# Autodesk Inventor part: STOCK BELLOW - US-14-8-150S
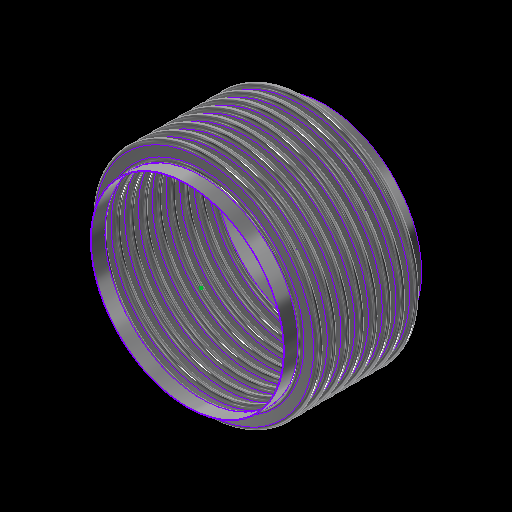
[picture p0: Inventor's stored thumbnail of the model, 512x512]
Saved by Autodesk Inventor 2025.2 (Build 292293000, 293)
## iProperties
Category: 16 GA (0.060 THICK)
RuleStatus: InUse
Created: 2024-01
Part Number: STOCK BELLOW - US-14-8-150S
Project: =STOCK BELLOWS: <Stock Number><SFILL>
Material: ASTM A240-304
Description: =STOCK BELLOWS: <Stock Number>, <SID_> I.D., <SOD_> O.D., <SPLY_> PLY, <Category>, <SNET_CONS> CONS.<PITCH_><STANGENT_> TANGENT<SFILL>
Document SubType Name: Sheet Metal
Designer: GS
Stock Number: U.S-14-8-150S
Surface Area: 15835.5 cm^2
Volume: 1198.85 cm^3
Sheet Metal Rule: Default
Appearance: STAINLESS STEEL
Mass: 9659.48 g
Density: 8.05729 g/cm^3
THK: 0.036
ID: 3.500
OD: 4.250
CONS_: 2
PITCH: 0.500
TANGENT: 0.500
BELLOWS_UPSET: 0.000
d79: 1.000
d82: 1.000
d83: 26.000
d84: 24.000
d174: 8
d214: 8
STHK_: 0.060
SID_: 14.000
SOD_: 16.500
SPITCH_: 1.000
STANGENT__: 1.000
SBELLOWS_UPSET_: 0.000
SDIFF_TAN: 1.000
d252: 2
d275: 2
d287: 0.050
d289: 0.500
d290: 0.000
SOD_NECK: 14 1/8
PLY: 1
PSET: 4.178
PBAR: 1.035
COUNTER: 1.500
NET_TUBE: 3.071
CONS: 2
S_CONS: 0
NET_CONS: 2
ID_M: 88.90 mm
OD_M: 107.95 mm
THK_M: 0.91 mm
ID_U: 3.500 in
OD_U: 4.250 in
THK_U: 0.036 in
TANGENT2: 0.500
TAN_TO_TAN: 1.000 in
d80: 2.571
d81: 10
SID: 2.375
SCONS_: 8
SPITCH: 0.250
STANGENT_: 1.000
SBELLOWS_UPSET: 0.000
SNET_CONS: 8
SS_CONS: 0
SCONS: 8
d190: 8
d191: 1
d192: 1
d193: 8
d194: 0
SIZE: 14.00
PRESSURE: 150
d230: 8
STANGENT: 4.000
SPLY_: 1
d233: 8
d234: 0
d263: 2
d265: 1
d268: 2
d269: 0
d286: 2
d288: 1
d291: 2
d292: 0
SREROLL: 0.750
BLETP: 0.000 ul
PRES_Copy: 85
MATTABLE: 20 GA (0.036 THICK)
PART_NUMBER: U.S-14-8-150S
PITCH_: =, <SPITCH_> PITCH,
CFILL: .
SFILL: .
MESH: ,
COMP: 1.53
EXT: 0.77
LAT: 0.26
ANG: 573
ASR: 3894
LSR: 19100
ANSR: 1778
PRES: 150
COMPM: 15.3
EXTM: 7.65
LATM: 2.60
ASRM: 681.956
PRESM: 10.342
LSRM: 3344.983
ANSRM: 311.381
TEMPMIN: 20
TEMPMAX: 800
TEMPMINM: -7
TEMPMAXM: 427
WEIGHTM: 9.659
WEIGHT: 21.296
Author: GS
Keywords: 20 GA (0.036 THICK)
Comments: =STOCK BELLOW - <STOCK NUMBER>
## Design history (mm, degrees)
sketch "Sketch2"
  geometry: L1 (0, -177.245)-(0, 562.856) reference; L2 (45.364, 0)-(44.45, 0); L3 (48.082, -2.718)-(50.343, -2.718); L4 (48.082, -3.632)-(50.343, -3.632); L5 (50.343, -9.982)-(48.082, -9.982); L6 (50.343, -9.068)-(48.082, -9.068); L7 (45.364, -12.7)-(44.45, -12.7); L8 (48.082, 0)-(48.082, -12.7); L9 (50.343, -6.35)-(53.975, -6.35); L10 (44.45, 0)-(44.45, -12.7); L11 (20.376, 102.841)-(20.376, 101.926); L12 (58.262, 457.127)-(58.262, 349.177); L13 (58.262, 444.427)-(58.262, 336.477); L14 (93.133, -58.817)-(93.133, -71.517); L15 (118.746, -66.401)-(118.746, -66.401); L16 (50.343, -9.068)-(50.343, -9.982); L17 (48.082, -9.068)-(48.082, -9.982); L18 (48.082, -9.525)-(50.343, -9.525); L19 (53.975, 0)-(53.975, -12.7); L20 (-50.343, -9.068)-(-50.343, -9.982); L21 (-50.343, -2.718)-(-48.082, -2.718); L22 (-50.343, -3.632)-(-48.082, -3.632); L23 (-48.082, -9.068)-(-50.343, -9.068); L24 (-50.343, -9.525)-(-48.082, -9.525); L25 (-48.082, -9.982)-(-50.343, -9.982); L26 (-48.082, -9.068)-(-48.082, -9.982); L27 (-44.45, 0.653)-(-44.45, -12.047); L28 (-48.082, -6.35)-(-44.45, -6.35); L29 (-50.343, 0.653)-(-50.343, -12.7); L30 (-53.061, 0)-(-53.975, 0); L31 (-53.975, 0)-(-53.975, -12.7); L32 (-53.061, -12.7)-(-53.975, -12.7); A1 r 2.718 centre (48.082, 0) between (45.364, 0) and (48.082, -2.718); A2 r 3.632 centre (48.082, 0) between (44.45, 0) and (48.082, -3.632); A3 r 3.632 centre (50.343, -6.35) between (50.343, -9.982) and (50.343, -2.718); A4 r 2.718 centre (50.343, -6.35) between (50.343, -9.068) and (50.343, -3.632); A5 r 2.718 centre (48.082, -12.7) between (48.082, -9.982) and (45.364, -12.7); A6 r 3.632 centre (48.082, -12.7) between (48.082, -9.068) and (44.45, -12.7); A7 r 3.175 centre (50.343, -6.35) between (50.343, -9.525) and (53.518, -6.35); A8 r 3.175 centre (48.082, -12.7) between (48.082, -9.525) and (44.907, -12.7); A9 r 2.718 centre (-50.343, -12.7) between (-50.343, -9.982) and (-53.061, -12.7); A10 r 2.718 centre (-48.082, -6.35) between (-48.082, -9.068) and (-48.082, -3.632); A11 r 3.175 centre (-48.082, -6.35) between (-48.082, -9.525) and (-44.907, -6.35); A12 r 3.632 centre (-48.082, -6.35) between (-48.082, -9.982) and (-48.082, -2.718); A13 r 3.175 centre (-50.343, -12.7) between (-50.343, -9.525) and (-53.518, -12.7); A14 r 3.632 centre (-50.343, -12.7) between (-50.343, -9.068) and (-53.975, -12.7); A15 r 2.718 centre (-50.343, 0) between (-53.061, 0) and (-50.343, -2.718); A16 r 3.632 centre (-50.343, 0) between (-53.975, 0) and (-50.343, -3.632); 10 further points
  constraints: 62 end point, 38 point on circle, 20 tangent, 16 centre point, 12 parallel, 9 midpoint, 7 vertical, 6 coincident, 6 concentric, 6 point on line, 4 equal radius, 4 perpendicular, 3 horizontal, 1 collinear, 1 horizontal alignment, 10 other
  dimensions: "THK" = 0.9144 distance of L11.start L11.end; "ID" = 88.9 distance of L11.end point (20.376, 13.026); "OD" = 107.95 distance of L12.start L12.end; "PITCH" = 12.7 distance of L12.start L13.start; "TANGENT" = 12.7 distance of L14.start L14.end; "BELLOWS_UPSET" = 0 distance of L15.start L15.end; "d43" = 88.9 diameter of L10 L1 (= ID); "d44" = 107.95 diameter of L9.end L1 (= OD); "d45" = 0.9144 distance between parallel lines of L5 L6 (computed from THK, PLY); "d46" = 3.6322 radius of A3 (computed from PITCH, THK, PLY); "UPSET_PITCH" = 12.7 distance of L2.end L7.end (derived); "SIDEWALL_ANGLE" = 360 deg dimension on L3 L9 (derived); "CON_GAP" = 5.4356 distance of point (48.082, -9.068) point (48.082, -3.632) (derived); "TAN1" = 4.98728 dimension on A8 (derived); "TAN2" = 4.98728 dimension on A7 (derived); "LEG1" = 2.2606 distance of L18.start L18.end (derived); "d278" = 0.9144 distance between parallel lines of L25 L23 (derived); "d279" = 3.6322 radius of A12 (derived); "d280" = 12.7 distance of L30.end L31.end (derived); "d281" = 360 deg dimension on L21 L28 (derived); "d282" = 5.4356 distance of point (-50.343, -9.068) point (-50.343, -3.632) (derived); "d283" = 4.98728 dimension on A13 (derived); "d284" = 4.98728 dimension on A11 (derived); "d285" = 2.2606 distance of L24.start L24.end (derived); "d293" = 88.9 diameter of L27 L1 (derived); "d294" = 107.95 diameter of L31 L1 (derived)
  node "Sketch Rectangular Pattern1" dims "d31" = 25.4, "ID" = 88.9
  node "Sketch Rectangular Pattern2" dims "d39" = 25.4, "PITCH" = 12.7
revolve "CONS" stored, may be unused: angle "d48" = 90 deg
node "BELLOW MIDPLANE"
pattern_linear "Rectangular Pattern2" dims "d52" = 12.7 (= UPSET_PITCH)
sketch "Sketch5"
  geometry: C1 r 45.364 at (0, 0) reference; C2 r 44.45 at (0, 0) reference
extrude "TANGENT" new body sketch "Sketch5" distance "d53" = 12.7 (= TANGENT); taper "d54" = 0 deg
revolve "SAMETAN" stored, may be unused: angle "d65" = 90 deg
revolve "DIFFTAN" stored, may be unused: angle "d70" = 90 deg
sketch "Sketch9"
  geometry: L1 (53.319, 0)-(-53.319, 0) reference; L2 (0, -17.78)-(0, 17.78) reference; L3 (38.085, 0)-(-38.085, 0); L4 (38.085, -11.906)-(38.085, 11.906); L5 (25.385, -11.906)-(25.385, 11.906); L6 (13.15, 11.906)-(13.15, -11.906); L7 (-25.385, -11.906)-(-25.385, 11.906); L8 (-38.085, -11.906)-(-38.085, 11.906); L9 (37.291, -11.906)-(37.291, 11.906); L10 (38.085, -11.906)-(37.291, -11.906); L11 (38.085, 11.906)-(37.291, 11.906); L12 (13.546, 11.906)-(12.753, 11.906); L13 (12.753, 11.906)-(12.753, -11.906); L14 (12.753, -11.906)-(13.546, -11.906); L15 (13.546, -11.906)-(13.546, 11.906); L16 (-13.546, 11.906)-(-13.546, -11.906); L17 (-13.15, 11.906)-(-13.15, -11.906); L18 (-13.546, -11.906)-(-12.753, -11.906); L19 (-12.753, -11.906)-(-12.753, 11.906); L20 (-12.753, 11.906)-(-13.546, 11.906); L21 (-38.085, -11.906)-(-37.291, -11.906); L22 (-37.291, -11.906)-(-37.291, 11.906); L23 (-37.291, 11.906)-(-38.085, 11.906); L24 (-38.085, 11.906)-(-38.085, -11.906); L25 (38.085, -0.397)-(-38.085, -0.397); L26 (-38.085, -0.397)-(-38.085, 0.397); L27 (-38.085, 0.397)-(38.085, 0.397); L28 (38.085, 0.397)-(38.085, -0.397); L29 (-38.085, 11.906)-(38.085, 11.906); L30 (38.085, 11.906)-(38.085, 12.7); L31 (38.085, 12.7)-(-38.085, 12.7); L32 (-38.085, 12.7)-(-38.085, 11.906); L33 (38.085, -11.906)-(-38.085, -11.906); L34 (-38.085, -11.906)-(-38.085, -12.7); L35 (-38.085, -12.7)-(38.085, -12.7); L36 (38.085, -12.7)-(38.085, -11.906); 30 further points
  constraints: 68 end point, 13 midpoint, 13 parallel, 8 horizontal, 7 perpendicular, 6 equal length, 3 point on line, 2 vertical, 14 other
  dimensions: "d115" = 23.8125 distance of L4.start L4.end (derived); "d116" = 12.7 distance between parallel lines of L4 L5 (derived); "d117" = 12.23516 distance between parallel lines of L5 L6 (derived); "d125" = 38.53427 distance between parallel lines of L7 L6 (derived); "d127" = 12.7 distance between parallel lines of L8 L7 (derived); "d128" = 24.93516 distance between parallel lines of L6 L4 (derived); "d130" = 76.16943 distance between parallel lines of L8 L4 (derived); "RULER_THK" = 0.79375 distance between parallel lines of L4 L9; "d135" = 0.79375 distance of L13.end L14.end (derived); "d138" = 26.29911 distance of L13.end L16.end (derived); "d143" = 0.79375 distance of L22.end L8.end (derived); "d144" = 0.79375 distance between parallel lines of L27 L25 (derived)
extrude "RULER" join sketch "Sketch9" distance "d149" = 0.79375 (derived); taper "d150" = 0 deg
extrude "BARS" join sketch "Sketch9" distance "d151" = 0.79375 (derived); taper "d152" = 0 deg
pattern_linear "Rectangular Pattern4" dims "d155" = 26.29911 (derived)
sketch "Sketch13"
  geometry: L1 (93.149, -52.467)-(93.149, -77.867); L2 (179.324, 0)-(177.8, 0); L3 (179.324, -25.4)-(177.8, -25.4); L4 (202.438, -19.812)-(184.912, -19.812); L5 (202.438, -18.288)-(184.912, -18.288); L6 (202.438, -12.7)-(209.55, -12.7); L7 (184.912, -5.588)-(202.438, -5.588); L8 (184.912, 0)-(184.912, -25.4); L9 (177.8, 0)-(177.8, -25.4); L10 (58.254, -77.331)-(58.254, -496.431); L11 (58.254, -102.731)-(58.254, -521.831); L12 (58.254, -153.531)-(58.254, -572.631); L13 (58.254, -178.931)-(58.254, -598.031); L14 (58.254, -204.331)-(58.254, -623.431); L15 (58.254, -229.731)-(58.254, -648.831); L16 (58.254, -255.131)-(58.254, -674.231); L17 (58.254, -128.131)-(58.254, -547.231); L18 (20.376, 103.45)-(20.376, 101.926); L19 (184.912, -7.112)-(202.438, -7.112); L20 (0, -829.767)-(0, 258.986) reference; L21 (-41.91, 0)-(251.46, 0) reference; A1 r 5.588 centre (184.912, 0) between (179.324, 0) and (184.912, -5.588); A2 r 5.588 centre (184.912, -25.4) between (184.912, -19.812) and (179.324, -25.4); A3 r 7.112 centre (184.912, -25.4) between (184.912, -18.288) and (177.8, -25.4); A4 r 5.588 centre (202.438, -12.7) between (202.438, -18.288) and (202.438, -7.112); A5 r 7.112 centre (202.438, -12.7) between (202.438, -19.812) and (202.438, -5.588); A6 r 7.112 centre (184.912, 0) between (177.8, 0) and (184.912, -7.112); 6 further points; 1 other entity
  constraints: 38 end point, 15 point on circle, 9 tangent, 6 centre point, 6 parallel, 5 vertical alignment, 4 point on line, 4 vertical, 3 coincident, 3 concentric, 2 collinear, 2 equal radius, 1 horizontal, 1 perpendicular, 23 other
  dimensions: "SBELLOWS_UPSET_" = 0 distance of point (118.762, -66.401) point (118.762, -66.401); "STOTAL_THK_BELLOW__" = 1.524 distance between parallel lines of L4 L5 (derived); "d224" = 7.112 radius of A5 (derived); "d225" = 25.4 distance of L2.end L3.end (derived); "SSIDEWALL_ANGLE_" = 360 deg dimension on L7 L6 (derived); "SSCON_GAP_" = 11.176 distance of point (184.912, -18.288) point (184.912, -7.112) (derived); "d235" = 355.6 diameter of L9 L20 (derived); "d236" = 419.1 diameter of L6.end L20 (derived)
  node "Sketch Rectangular Pattern4" dims "d228" = 25.4
  node "Sketch Rectangular Pattern5" dims "d229" = 25.4
revolve "SBELLOW" stored, may be unused: angle "d197" = 90 deg
pattern_linear "Rectangular Pattern5" dims "d204" = 25.4 (derived)
revolve "STANGENT" stored, may be unused: angle "d240" = 90 deg
revolve "SSAMETAN" stored, may be unused: angle "d241" = 90 deg
revolve "SDIFFTAN" stored, may be unused: angle "d246" = 90 deg
revolve "INVCON" stored, may be unused: angle "d295" = 90 deg
pattern_linear "Rectangular Pattern6" dims "d298" = 12.7 (derived)
revolve "INVTANGENT" stored, may be unused: angle "d302" = 90 deg
revolve "INVSAMETAN" stored, may be unused: angle "d307" = 90 deg
revolve "INVDIFFTAN" stored, may be unused: angle "d312" = 90 deg
sketch "ID BELLOW MOUNT CALC"
  geometry: L1 (44.45, 0)-(38.1, 0); L2 (38.1, 0)-(38.1, 12.7); L3 (38.1, 12.7)-(44.45, 12.7); L4 (44.45, 12.7)-(44.45, 0); L5 (36.513, 12.7)-(35.598, 12.7); L6 (35.598, 12.7)-(35.598, 0); L7 (35.598, 0)-(36.513, 0); L8 (36.513, 0)-(36.513, 12.7); L9 (0, -2.54)-(0, 15.24) reference; L10 (-8.89, 0)-(53.34, 0) reference; 1 further point
  constraints: 16 end point, 5 parallel, 2 collinear, 2 horizontal, 2 perpendicular
  dimensions: "d314" = 12.7 distance of L5.end L6.end (derived); "d315" = 0.9144 distance of L5.start L5.end (derived); "IG" = 1.5875 distance between parallel lines of L2 L8; "PIPE_OD" = 88.9 diameter of L4 L9; "PIPE_WALL" = 6.35 distance of L2.end L3.end; "ID_MT_BELLOW" = 71.1962 diameter of L6 L9 (derived)
revolve "CFILL" stored, may be unused: angle "d320" = 90 deg
pattern_linear "Rectangular Pattern7" dims "d323" = 12.7 (derived)
revolve "SFILL" stored, may be unused: angle "d324" = 90 deg
pattern_linear "Rectangular Pattern8" dims "d327" = 25.4 (derived)
node "STOCK BELLOW MIDPLANE"
node "BELLOW"
sketch "Sketch6"
  geometry: L1 (-12.7, 45.364)-(0, 45.364); L2 (0, 45.364)-(0, 44.45); L3 (0, 44.45)-(-12.7, 44.45); L4 (-12.7, 44.45)-(-12.7, 45.364); L5 (10.16, 0)-(-60.96, 0) reference; L6 (-38.1, -89.422)-(-38.1, 153.44) reference; 1 further point
  constraints: 8 end point, 2 parallel, 1 horizontal, 1 perpendicular
  dimensions: "d61" = 12.7 distance of L2.end L3.end (derived); "d62" = 0.9144 distance of L1.end L2.end (derived); "d63" = 88.9 diameter of L3 L5 (derived); "d64" = 25.4 distance between parallel lines of L4 L6 (derived)
sketch "Sketch12"
  geometry: 1 further point
sketch "Sketch14"
  geometry: L1 (-25.4, 179.324)-(0, 179.324); L2 (0, 179.324)-(0, 177.8); L3 (0, 177.8)-(-25.4, 177.8); L4 (-25.4, 177.8)-(-25.4, 179.324); L5 (5.08, 0)-(-30.48, 0) reference; L6 (0, -35.865)-(0, 215.189) reference; 1 further point
  constraints: 8 end point, 2 parallel, 1 collinear, 1 horizontal, 1 perpendicular
  dimensions: "d237" = 1.524 distance of L3.end L1.start (derived); "d238" = 355.6 diameter of L3 L5 (derived); "d239" = 25.4 distance of L1.start L1.end (derived); "SOD_NECK" = 358.648 diameter of L1 L5 (derived)
sketch "Sketch15"
  geometry: L1 (-35.865, 0)-(215.189, 0) reference; L2 (177.8, -203.2)-(179.324, -203.2); L3 (179.324, -203.2)-(179.324, -228.6); L4 (179.324, -228.6)-(177.8, -228.6); L5 (177.8, -228.6)-(177.8, -203.2); L6 (0, -276.86)-(0, 60.96) reference; 1 further point
  constraints: 8 end point, 2 parallel, 1 horizontal, 1 perpendicular
  dimensions: "d205" = 25.4 distance of L4.end L2.start (derived); "d206" = 1.524 distance of L3.end L4.end (derived); "d207" = 355.6 diameter of L5 L6 (derived); "d208" = 203.2 distance between parallel lines of L1 L2 (derived)
node "TANGENT_"
node "SAME_TAN"
sketch "Sketch8"
  geometry: L1 (45.364, -25.4)-(44.45, -25.4); L2 (44.45, -25.4)-(44.45, -38.1); L3 (44.45, -38.1)-(45.364, -38.1); L4 (45.364, -38.1)-(45.364, -25.4); L5 (0, -48.26)-(0, 22.86) reference; L6 (-89.422, 0)-(153.44, 0) reference; 1 further point
  constraints: 8 end point, 2 parallel, 1 horizontal, 1 perpendicular
  dimensions: "d66" = 88.9 diameter of L2 L5 (derived); "TOTAL_THK_BELLOW" = 0.9144 distance of L2.end L3.end (derived); "d68" = 25.4 distance between parallel lines of L1 L6 (derived); "d69" = 12.7 distance of L1.end L2.end (derived)
node "DIFF_TAN"
node "Sketch Rectangular Pattern3" dims "d138" = 26.29911 (derived), "d141" = 25.4
node "SBELLOW_"
node "STANGENT_"
node "SSAME_TAN"
sketch "Sketch16"
  geometry: L1 (179.324, -203.2)-(177.8, -203.2); L2 (177.8, -203.2)-(177.8, -228.6); L3 (177.8, -228.6)-(179.324, -228.6); L4 (179.324, -228.6)-(179.324, -203.2); L5 (0, -276.86)-(0, 60.96) reference; L6 (-35.865, 0)-(215.189, 0) reference; 1 further point
  constraints: 8 end point, 2 parallel, 1 horizontal, 1 perpendicular
  dimensions: "SDIFF_TAN" = 25.4 distance of L3.end L1.start; "d243" = 1.524 distance of L2.end L3.end (derived); "d244" = 203.2 distance between parallel lines of L1 L6 (derived); "d245" = 355.6 diameter of L2 L5 (derived)
node "SDIFF_TAN"
body "Solid15"
sketch "Sketch17"
  geometry: L1 (53.975, 12.7)-(53.061, 12.7); L2 (53.061, 12.7)-(53.061, 0); L3 (53.061, 0)-(53.975, 0); L4 (53.975, 0)-(53.975, 12.7); L5 (0, -2.54)-(0, 15.24) reference; L6 (-10.795, 0)-(64.77, 0) reference; 2 further points
  constraints: 8 end point, 2 parallel, 1 horizontal, 1 midpoint, 1 perpendicular, 1 point on line
  dimensions: "INVTANGENT" = 12.7 distance of L3.end L1.start (derived); "d300" = 0.9144 distance of L1.start L1.end (derived); "d301" = 107.95 diameter of L4 L5 (derived)
body "Solid16"
sketch "Sketch18"
  geometry: L1 (53.975, -25.4)-(53.061, -25.4); L2 (53.061, -25.4)-(53.061, -38.1); L3 (53.061, -38.1)-(53.975, -38.1); L4 (53.975, -38.1)-(53.975, -25.4); L5 (-10.795, 0)-(64.77, 0) reference; L6 (0, -48.26)-(0, 22.86) reference; 1 further point
  constraints: 8 end point, 2 parallel, 1 horizontal, 1 perpendicular
  dimensions: "d303" = 25.4 distance between parallel lines of L1 L5 (derived); "d304" = 12.7 distance of L3.end L1.start (derived); "d305" = 0.9144 distance of L2.end L3.end (derived); "d306" = 107.95 diameter of L4 L6 (derived)
body "Solid17"
sketch "Sketch19"
  geometry: L1 (53.975, -25.4)-(53.061, -25.4); L2 (53.061, -25.4)-(53.061, -38.1); L3 (53.061, -38.1)-(53.975, -38.1); L4 (53.975, -38.1)-(53.975, -25.4); L5 (0, -48.26)-(0, 22.86) reference; L6 (-10.795, 0)-(64.77, 0) reference; 1 further point
  constraints: 8 end point, 2 parallel, 1 horizontal, 1 perpendicular
  dimensions: "d308" = 12.7 distance of L1.end L2.end (derived); "d309" = 107.95 diameter of L4 L5 (derived); "d310" = 0.9144 distance of L2.end L3.end (derived); "d311" = 25.4 distance between parallel lines of L1 L6 (derived)
body "Solid18"
body "Solid19"
body "Solid20"
other parameters: "BMPL" = -101.6, "PSET" = 106.1212 (computed from OD, THK, PLY) [user parameter], "PBAR" = 26.29911 (= 0.570796 x PITCH + OD - ID) [user parameter; used in 1 equation term], "COUNTER" = 15 [user parameter], "NET_TUBE" = 77.99823 (computed from CONS_, PBAR, TANGENT) [user parameter], "S_CONS" = 0 [user parameter; used in 1 equation term], "ID_M" = 88.9 (= ID) [user parameter], "OD_M" = 107.95 (= OD) [user parameter], "THK_M" = 0.9144 (= THK) [user parameter], "ID_U" = 88.9 (= ID) [user parameter], "OD_U" = 107.95 (= OD) [user parameter], "THK_U" = 0.9144 (= THK) [user parameter], "D_UNITS" = 0 [user parameter], "TANGENT2" = 12.7 [user parameter], "TAN_TO_TAN" = 25.4 [user parameter], "OD_NECK" = 90.7288 [user parameter], "d79" = 25.4, "d80" = 65.29823 [user parameter], "d82" = 25.4, "d83" = 660.4, "d84" = 609.6, "sa_0" = 4, "FRAME_THK" = 0.79375 [user parameter], "CON_FLAT" = 12.23516 [user parameter], "SID" = 60.325 [user parameter], "SPITCH" = 6.35 [user parameter], "STANGENT_" = 25.4 [user parameter], "SBELLOWS_UPSET" = 0 [user parameter], "SS_CONS" = 0 [user parameter], "STAN_TO_TAN_" = 203.2 [user parameter], "d100" = 1.524 [user parameter], "d191" = 25.4 [user parameter], "d194" = 0 [user parameter], "STANGENT" = 101.6 [user parameter], "d234" = 0 [user parameter], "SUPSET_PITCH_" = 25.4 [user parameter], "d269" = 0 [user parameter], "d287" = 1.27, "d289" = 12.7, "d290" = 0, "d292" = 0 [user parameter], "Thickness" = 3.048 (derived), "KFactor" = 4.4, "BendRadius" = 3.048 (derived), "BendReliefWidth" = 3.048 (derived), "BendReliefDepth" = 1.524 (derived), "CornerReliefSize" = 12.192 (derived), "SeamGap" = 0.00508, "MinimumRemnant" = 6.096 (derived), "TransitionRadius" = 3.048 (derived), "JacobiRadiusSize" = 3.048 (derived), "GapSize" = 3.048 (derived), "SREROLL" = 19.05 [user parameter], "CUR_STK_PITCH" = 25.4 [user parameter], "d328" = -101.6 (derived), "ASR" = 38940 [user parameter], "LSR" = 191000 [user parameter], "ANSR" = 17780 [user parameter], "BLETP" = 0 [user parameter], "ASRM" = 6819.5622 [user parameter], "PRESM" = 103.41975 [user parameter], "LSRM" = 33449.83 [user parameter], "ANSRM" = 3113.8114 [user parameter], "TEMPMIN" = 2664.83333 [user parameter], "TEMPMAX" = 6998.16667 [user parameter], "TEMPMINM" = 2664.83333 [user parameter], "TEMPMAXM" = 6998.16667 [user parameter], "WEIGHT" = 96.59484 [user parameter], "WEIGHTM" = 0.09659 [user parameter]
